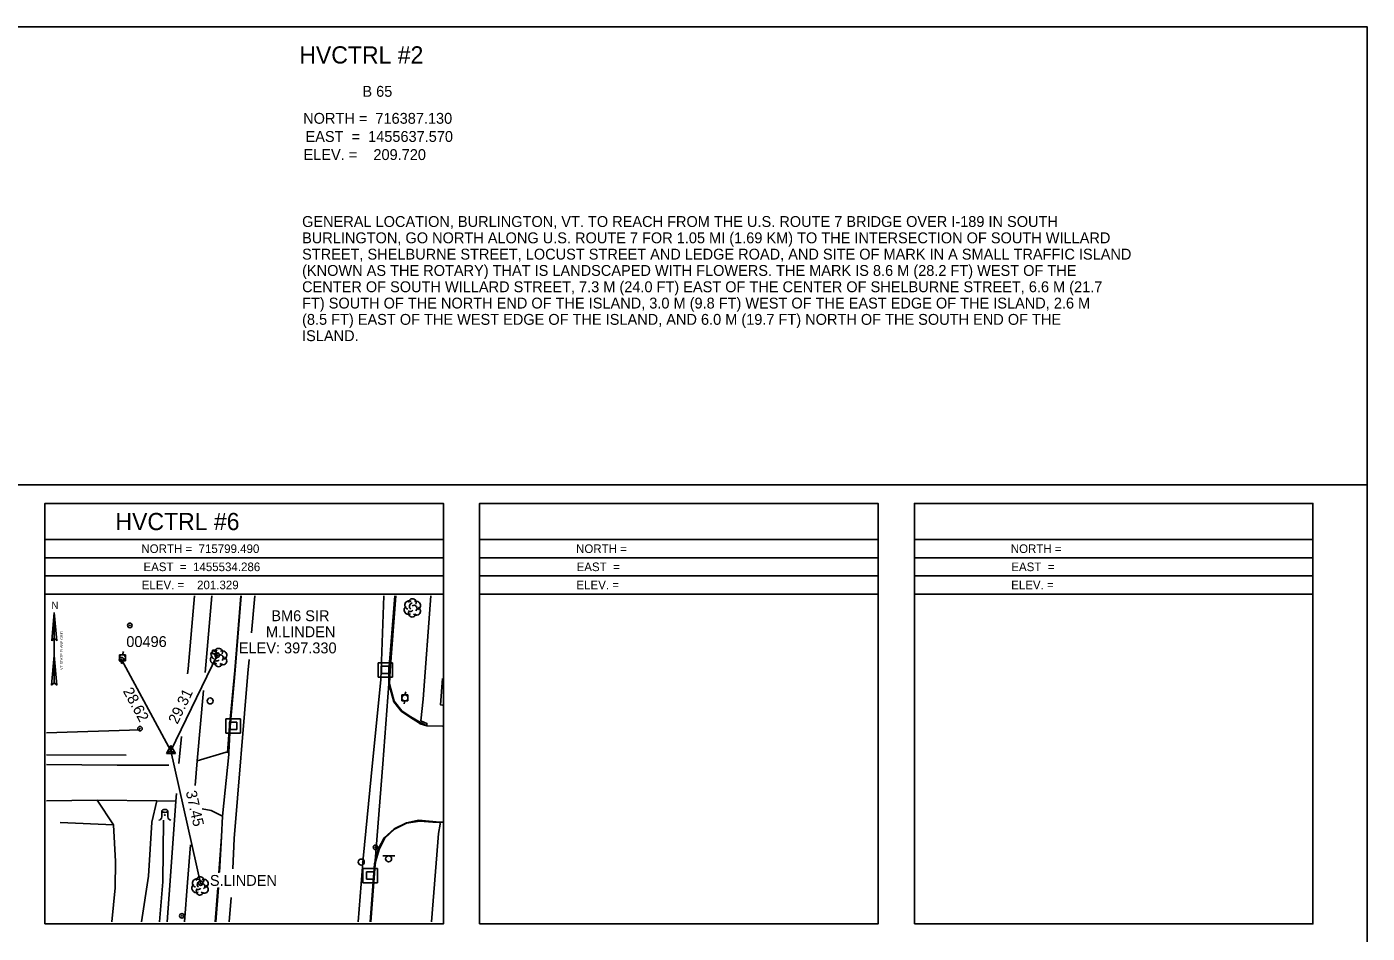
# Model space of a CAD drawing. Extents: x 1454512 to 1455152, y 715836 to 716256.
# Drawn here: x 1454782.2 to 1455152.2, y 716005.4 to 716255.5 of the extents above; entities that cross this region are included whole.
import ezdxf

# ---------------------------------------------------------------- set-up
doc = ezdxf.new("R2010")
doc.units = 0
for name, color, linetype in [('C_C', 7, 'Continuous'), ('CBP', 7, 'Continuous'), ('CPBM', 7, 'Continuous'), ('CPSM', 7, 'Continuous'), ('Default', 7, 'Continuous'), ('DS', 7, 'Continuous'), ('L_C', 7, 'Continuous'), ('LAHR', 7, 'Continuous'), ('LAPB', 7, 'Continuous'), ('LFNC', 7, 'Continuous'), ('LTD', 7, 'Continuous'), ('LTS', 7, 'Continuous'), ('MPIP', 7, 'Continuous'), ('NBL1', 7, 'Continuous'), ('NBL2', 7, 'Continuous'), ('NNA_P', 7, 'Continuous'), ('PET', 7, 'Continuous'), ('PSP', 7, 'Continuous'), ('RC', 7, 'Continuous'), ('RDG', 7, 'Continuous'), ('RDP', 7, 'Continuous'), ('RSW', 7, 'Continuous'), ('SSGN', 7, 'Continuous'), ('U_C', 7, 'Continuous'), ('UP', 7, 'Continuous'), ('UPGW', 7, 'Continuous'), ('UTMH', 7, 'Continuous'), ('UUMH', 7, 'Continuous'), ('UWV', 7, 'Continuous')]:
    doc.layers.add(name, color=color, linetype=linetype)

msp = doc.modelspace()

# ---------------------------------------------------------------- linework, layer by layer
at = {"layer": 'CBP'}
for centre, radius in [((1454808.28, 716080.9), 0.625), ((1454808.28, 716080.9), 0.0833), ((1454834.71, 716082.14), 0.625), ((1454834.71, 716082.14), 0.0833), ((1454830.15, 716019.22), 0.625), ((1454830.15, 716019.22), 0.0833)]:
    msp.add_circle(centre, radius, dxfattribs=at)
at = {"layer": 'CPBM'}
for p, q in [((1454833.46, 716082.5), (1454833.46, 716083.5)), ((1454833.46, 716083.5), (1454834.46, 716083.5)), ((1454834.46, 716082.5), (1454833.46, 716082.5)), ((1454833.96, 716083), (1454833.96, 716083)), ((1454833.96, 716083), (1454833.96, 716083)), ((1454834.46, 716083.5), (1454834.46, 716082.5))]:
    msp.add_line(p, q, dxfattribs=at)
at = {"layer": 'CPSM'}
for p, q in [((1454820.68, 716055.04), (1454821.93, 716057.2)), ((1454820.68, 716055.04), (1454821.93, 716055.76)), ((1454820.68, 716055.04), (1454823.18, 716055.04)), ((1454823.18, 716055.04), (1454821.93, 716057.2)), ((1454821.93, 716055.76), (1454821.93, 716057.2)), ((1454821.93, 716055.76), (1454821.93, 716055.76)), ((1454821.93, 716055.76), (1454823.18, 716055.04))]:
    msp.add_line(p, q, dxfattribs=at)
at = {"layer": 'Default'}
for p, q in [((1454808.28, 716080.9), (1454821.93, 716055.76)), ((1454821.93, 716055.76), (1454834.71, 716082.14)), ((1454821.93, 716055.76), (1454830.15, 716019.22))]:
    msp.add_line(p, q, dxfattribs=at)
at = {"layer": 'DS'}
for p, q in [((1454879.11, 716080.07), (1454883.11, 716080.07)), ((1454879.11, 716076.07), (1454879.11, 716080.07)), ((1454880.11, 716077.07), (1454880.11, 716079.07)), ((1454880.11, 716079.07), (1454882.11, 716079.07)), ((1454882.11, 716077.07), (1454880.11, 716077.07)), ((1454881.11, 716078.07), (1454881.11, 716078.07)), ((1454881.11, 716078.07), (1454881.11, 716078.07)), ((1454882.11, 716079.07), (1454882.11, 716077.07)), ((1454883.11, 716080.07), (1454883.11, 716076.07)), ((1454883.11, 716076.07), (1454879.11, 716076.07)), ((1454837.12, 716064.61), (1454841.12, 716064.61)), ((1454837.12, 716060.61), (1454837.12, 716064.61)), ((1454838.12, 716061.61), (1454838.12, 716063.61)), ((1454838.12, 716063.61), (1454840.12, 716063.61)), ((1454839.12, 716062.61), (1454839.12, 716062.61)), ((1454839.12, 716062.61), (1454839.12, 716062.61)), ((1454840.12, 716063.61), (1454840.12, 716061.61)), ((1454841.12, 716064.61), (1454841.12, 716060.61)), ((1454841.12, 716060.61), (1454837.12, 716060.61)), ((1454840.12, 716061.61), (1454838.12, 716061.61)), ((1454874.95, 716023.32), (1454878.95, 716023.32)), ((1454874.95, 716019.32), (1454874.95, 716023.32)), ((1454875.95, 716020.32), (1454875.95, 716022.32)), ((1454875.95, 716022.32), (1454877.95, 716022.32)), ((1454876.96, 716021.32), (1454876.96, 716021.32)), ((1454876.96, 716021.32), (1454876.96, 716021.32)), ((1454877.95, 716022.32), (1454877.95, 716020.32)), ((1454878.95, 716023.32), (1454878.95, 716019.32)), ((1454878.95, 716019.32), (1454874.95, 716019.32)), ((1454877.95, 716020.32), (1454875.95, 716020.32))]:
    msp.add_line(p, q, dxfattribs=at)
at = {"layer": 'LAHR'}
msp.add_lwpolyline([(1454819.92, 716036.65), (1454819.67, 716019.64), (1454818.78, 716008.54)], dxfattribs=at)
at = {"layer": 'LAPB'}
for points in [[(1454809.55, 716054.57), (1454787.6, 716054.67)], [(1454791.35, 716035.97), (1454806.11, 716035.34)]]:
    msp.add_lwpolyline(points, dxfattribs=at)
at = {"layer": 'LFNC'}
msp.add_lwpolyline([(1454813.33, 716061.51), (1454787.6, 716060.69)], dxfattribs=at)
at = {"layer": 'LTD'}
for p, q in [((1454888.56, 716095.25), (1454888.56, 716095.25)), ((1454888.56, 716095.25), (1454888.56, 716095.25)), ((1454835.08, 716081.55), (1454835.08, 716081.55)), ((1454835.08, 716081.55), (1454835.08, 716081.55)), ((1454829.96, 716018.52), (1454829.96, 716018.52)), ((1454829.96, 716018.52), (1454829.96, 716018.52))]:
    msp.add_line(p, q, dxfattribs=at)
for centre in [(1454888.61, 716096.68), (1454835.13, 716082.98), (1454830, 716019.96)]:
    msp.add_arc(centre, 1.05, 335.5272, 180.9563, dxfattribs=at)
for centre, major_axis, ratio, start_param, end_param in [((1454887.48, 716094.54), (0.58, -1.04), 0.959034, 3.141593, 6.283185), ((1454887.77, 716095.91), (1.21, -0.51), 0.895232, 1.570796, 4.712389), ((1454888.35, 716095.7), (-0.208, -0.792), 0.645439, 3.141593, 6.283185), ((1454889.06, 716095.08), (-0.5, 0.667), 0.989748, 3.141593, 6.283185), ((1454889.56, 716094.41), (-1.09, 0.79), 0.841452, 1.570796, 4.712389), ((1454889.6, 716095.83), (-1.14, -0.48), 0.949671, 1.570796, 4.712389), ((1454888.56, 716093.75), (0.26, 1.06), 0.942809, 1.570796, 4.712389), ((1454888.1, 716094.5), (-0.625, -0.083), 0.423636, 0, 3.141593), ((1454834, 716080.84), (0.58, -1.04), 0.959034, 3.141593, 6.283185), ((1454834.29, 716082.22), (1.21, -0.51), 0.895232, 1.570796, 4.712389), ((1454835.08, 716080.05), (0.26, 1.06), 0.942809, 1.570796, 4.712389), ((1454834.62, 716080.8), (-0.625, -0.083), 0.423636, 0, 3.141593), ((1454834.87, 716082.01), (-0.208, -0.792), 0.645439, 3.141593, 6.283185), ((1454835.58, 716081.38), (-0.5, 0.667), 0.989748, 3.141593, 6.283185), ((1454836.08, 716080.72), (-1.09, 0.79), 0.841452, 1.570796, 4.712389), ((1454836.12, 716082.13), (-1.14, -0.48), 0.949671, 1.570796, 4.712389), ((1454828.87, 716017.81), (0.58, -1.04), 0.959034, 3.141593, 6.283185), ((1454829.16, 716019.19), (1.21, -0.51), 0.895232, 1.570796, 4.712389), ((1454829.5, 716017.77), (-0.625, -0.083), 0.423636, 0, 3.141593), ((1454829.75, 716018.98), (-0.208, -0.792), 0.645439, 3.141593, 6.283185), ((1454830.46, 716018.36), (-0.5, 0.667), 0.989748, 3.141593, 6.283185), ((1454830.96, 716017.69), (-1.09, 0.79), 0.841452, 1.570796, 4.712389), ((1454831, 716019.11), (-1.14, -0.48), 0.949671, 1.570796, 4.712389), ((1454829.96, 716017.02), (0.26, 1.06), 0.942809, 1.570796, 4.712389)]:
    msp.add_ellipse(centre, major_axis=major_axis, ratio=ratio, start_param=start_param, end_param=end_param, dxfattribs=at)
at = {"layer": 'LTS'}
for p, q in [((1454819.44, 716039.16), (1454819.44, 716037.49)), ((1454820.27, 716038.01), (1454820.27, 716038.01)), ((1454820.27, 716038.01), (1454820.27, 716038.01)), ((1454820.27, 716037.99), (1454820.27, 716037.99)), ((1454821.11, 716038.99), (1454821.11, 716039.16)), ((1454821.11, 716039.16), (1454821.11, 716037.49))]:
    msp.add_line(p, q, dxfattribs=at)
msp.add_circle((1454820.27, 716038.01), 0.0833, dxfattribs=at)
for centre, start, end in [((1454818.61, 716037.49), 270, 360), ((1454821.94, 716037.49), 180, 270)]:
    msp.add_arc(centre, 0.833, start, end, dxfattribs=at)
msp.add_ellipse((1454820.27, 716039.16), major_axis=(-0.833, 0), ratio=0.5, dxfattribs=at)
at = {"layer": 'MPIP'}
for radius in [0.625, 0.0833]:
    msp.add_circle((1454813.39, 716061.85), radius, dxfattribs=at)
at = {"layer": 'NBL1'}
msp.add_lwpolyline([(1454512.16, 715835.51), (1455152.16, 715835.51), (1455152.16, 716255.51), (1454512.16, 716255.51)], close=True, dxfattribs=at)
at = {"layer": 'NBL2'}
for p, q in [((1454512.16, 716129.18), (1455152.16, 716129.18)), ((1454897.16, 716114.01), (1454787.16, 716114.01)), ((1455017.16, 716114.01), (1454907.16, 716114.01)), ((1455137.16, 716114.01), (1455027.16, 716114.01)), ((1454897.16, 716109.01), (1454787.16, 716109.01)), ((1455017.16, 716109.01), (1454907.16, 716109.01)), ((1455137.16, 716109.01), (1455027.16, 716109.01)), ((1454897.16, 716104.01), (1454787.16, 716104.01)), ((1455017.16, 716104.01), (1454907.16, 716104.01)), ((1455137.16, 716104.01), (1455027.16, 716104.01)), ((1454897.16, 716099.01), (1454787.16, 716099.01)), ((1455017.16, 716099.01), (1454907.16, 716099.01)), ((1455137.16, 716099.01), (1455027.16, 716099.01))]:
    msp.add_line(p, q, dxfattribs=at)
for points in [[(1454787.16, 716008.01), (1454897.16, 716008.01), (1454897.16, 716124.01), (1454787.16, 716124.01)], [(1454907.16, 716008.01), (1455017.16, 716008.01), (1455017.16, 716124.01), (1454907.16, 716124.01)], [(1455027.16, 716008.01), (1455137.16, 716008.01), (1455137.16, 716124.01), (1455027.16, 716124.01)]]:
    msp.add_lwpolyline(points, close=True, dxfattribs=at)
at = {"layer": 'NNA_P'}
for p, q in [((1454789.05, 716086.1), (1454789.74, 716093.89)), ((1454789.74, 716074.52), (1454789.74, 716093.89)), ((1454790.43, 716086.1), (1454789.74, 716093.89)), ((1454789.05, 716086.1), (1454789.74, 716086.87)), ((1454790.44, 716086.1), (1454789.74, 716086.87)), ((1454789.75, 716082.04), (1454789.02, 716073.88)), ((1454789.74, 716082.04), (1454790.47, 716073.88)), ((1454789.74, 716074.52), (1454789.02, 716073.88)), ((1454789.74, 716074.52), (1454790.47, 716073.88))]:
    msp.add_line(p, q, dxfattribs=at)
at = {"layer": 'PET'}
for points in [[(1454845.14, 716098.52), (1454844.2, 716088.3)], [(1454873.63, 716008.54), (1454875.04, 716026), (1454877.61, 716052.43), (1454879.88, 716075.33), (1454880.7, 716098.52)], [(1454843.53, 716080.98), (1454843.19, 716077.2), (1454839.38, 716031.53), (1454839, 716023.21)], [(1454896.9, 716062.53), (1454892.63, 716062.65), (1454890.78, 716063.22), (1454890.27, 716063.58), (1454888.08, 716064.93), (1454885.53, 716066.68), (1454883.5, 716069.31), (1454882.06, 716074.22)], [(1454878.29, 716025.43), (1454879.26, 716028.76), (1454880.85, 716031.78), (1454883.54, 716034.18), (1454887, 716035.91), (1454890.31, 716036.64), (1454894.25, 716036.27), (1454896.15, 716036.09), (1454896.9, 716036.07)], [(1454838.58, 716015.32), (1454838.06, 716008.54)]]:
    msp.add_lwpolyline(points, dxfattribs=at)
at = {"layer": 'PSP'}
for points in [[(1454841.36, 716098.52), (1454839.71, 716078), (1454838.33, 716062.5), (1454837.89, 716055.35), (1454837.89, 716054.72), (1454836.15, 716037.71), (1454835.94, 716032.05), (1454835.32, 716022.23)], [(1454876.91, 716008.54), (1454878.14, 716024.59), (1454878.29, 716025.43), (1454880.42, 716052.13), (1454882.06, 716074.22), (1454882.14, 716077.91), (1454883.78, 716098.52)], [(1454835.06, 716018.01), (1454834.33, 716008.54)]]:
    msp.add_lwpolyline(points, dxfattribs=at)
at = {"layer": 'RC'}
for points in [[(1454841.2, 716098.52), (1454839.61, 716077.94), (1454838.13, 716062.59), (1454837.6, 716055.32), (1454837.22, 716055.38)], [(1454890.93, 716064.06), (1454892.61, 716063.31), (1454892.63, 716062.65), (1454890.38, 716063.81), (1454888.19, 716065.1), (1454885.69, 716066.78), (1454883.61, 716069.48), (1454882.27, 716074.26), (1454882.48, 716077.93), (1454884.01, 716098.52)], [(1454877.11, 716008.54), (1454878.33, 716024.38), (1454878.5, 716025.42), (1454879.45, 716028.54), (1454880.99, 716031.62), (1454883.68, 716034.1), (1454887, 716035.8), (1454890.66, 716036.36), (1454894.24, 716036.09), (1454896.15, 716036.09), (1454896.24, 716035.49)], [(1454835.94, 716032.05), (1454835.17, 716022.06)], [(1454834.85, 716017.9), (1454834.13, 716008.54)]]:
    msp.add_lwpolyline(points, dxfattribs=at)
at = {"layer": 'RDG'}
for points in [[(1454801.57, 716042.16), (1454806.11, 716035.34), (1454806.6, 716025.24), (1454806.51, 716017.9), (1454805.59, 716008.54)], [(1454813.85, 716008.54), (1454815.79, 716021.19), (1454816.65, 716036.02), (1454818.05, 716041.94)]]:
    msp.add_lwpolyline(points, dxfattribs=at)
at = {"layer": 'RDP'}
for points in [[(1454837.22, 716055.38), (1454829.17, 716052.96)], [(1454787.6, 716052), (1454807.08, 716051.82), (1454821.41, 716051.8)], [(1454787.6, 716041.94), (1454801.57, 716042.16), (1454818.05, 716041.94), (1454823.3, 716041.87)], [(1454830.57, 716039.74), (1454833.01, 716039.31), (1454836.15, 716037.71)]]:
    msp.add_lwpolyline(points, dxfattribs=at)
at = {"layer": 'RSW'}
for points in [[(1454828.42, 716098.52), (1454826.66, 716078.36), (1454826.53, 716076.98)], [(1454833.22, 716098.52), (1454831.42, 716077.38)], [(1454890.93, 716064.06), (1454891.61, 716070.01), (1454893.68, 716098.52)], [(1454896.9, 716068.36), (1454896.36, 716068.41), (1454896.9, 716075.72)], [(1454830.96, 716072.4), (1454829.17, 716052.96), (1454828.62, 716046.21)], [(1454824.83, 716059.73), (1454824.09, 716052.25)], [(1454823.46, 716044.01), (1454823.3, 716041.87), (1454821.75, 716019.83), (1454820.87, 716008.54)], [(1454893.86, 716008.54), (1454895.61, 716030.58), (1454895.76, 716032.91), (1454896.24, 716035.49)], [(1454827.32, 716029.79), (1454826.52, 716019.41), (1454825.73, 716008.54)]]:
    msp.add_lwpolyline(points, dxfattribs=at)
at = {"layer": 'SSGN'}
for p, q in [((1454880.4, 716026.78), (1454883.73, 716026.78)), ((1454882.04, 716025.95), (1454882.04, 716025.95))]:
    msp.add_line(p, q, dxfattribs=at)
msp.add_circle((1454882.04, 716025.95), 0.833, dxfattribs=at)
at = {"layer": 'UP'}
for p, q in [((1454807.73, 716080.61), (1454807.73, 716082.27)), ((1454807.73, 716082.27), (1454809.39, 716082.27)), ((1454809.39, 716080.61), (1454807.73, 716080.61)), ((1454808.31, 716079.77), (1454808.56, 716080.61)), ((1454808.81, 716083.11), (1454808.56, 716082.27)), ((1454808.56, 716081.44), (1454808.56, 716081.44)), ((1454809.39, 716082.27), (1454809.39, 716080.61)), ((1454885.72, 716069.5), (1454885.72, 716071.17)), ((1454885.72, 716071.17), (1454887.38, 716071.17)), ((1454887.38, 716069.5), (1454885.72, 716069.5)), ((1454886.3, 716068.67), (1454886.55, 716069.5)), ((1454886.8, 716072), (1454886.55, 716071.17)), ((1454886.55, 716070.34), (1454886.55, 716070.34)), ((1454887.38, 716071.17), (1454887.38, 716069.5))]:
    msp.add_line(p, q, dxfattribs=at)
for centre in [(1454808.56, 716081.44), (1454886.55, 716070.34)]:
    msp.add_circle(centre, 0.833, dxfattribs=at)
at = {"layer": 'UPGW'}
for radius in [0.625, 0.0833]:
    msp.add_circle((1454810.59, 716090.35), radius, dxfattribs=at)
at = {"layer": 'UTMH'}
for p, q in [((1454832.77, 716069.51), (1454832.77, 716069.51)), ((1454833.6, 716069.51), (1454833.6, 716069.51))]:
    msp.add_line(p, q, dxfattribs=at)
msp.add_circle((1454832.77, 716069.51), 0.833, dxfattribs=at)
at = {"layer": 'UUMH'}
for p, q in [((1454874.49, 716025.04), (1454874.49, 716025.04)), ((1454875.33, 716025.04), (1454875.33, 716025.04))]:
    msp.add_line(p, q, dxfattribs=at)
msp.add_circle((1454874.49, 716025.04), 0.833, dxfattribs=at)
at = {"layer": 'UWV'}
for centre, radius in [((1454878.41, 716029.11), 0.625), ((1454878.41, 716029.11), 0.0833), ((1454824.97, 716010.23), 0.625), ((1454824.97, 716010.23), 0.0833)]:
    msp.add_circle(centre, radius, dxfattribs=at)

# ---------------------------------------------------------------- texts
at = {"layer": 'C_C'}
for s, p in [('BM6 SIR', (1454849.66, 716091.52)), ('M.LINDEN', (1454848.17, 716087.08)), ('ELEV: 397.330', (1454840.68, 716082.64))]:
    msp.add_text(s, height=3, dxfattribs=at).set_placement(p)
at = {"layer": 'Default'}
for s, p in [('GENERAL LOCATION, BURLINGTON, VT. TO REACH FROM THE U.S. ROUTE 7 BRIDGE OVER I-189 IN SOUTH ', (1454858.15, 716200.29)), ('BURLINGTON, GO NORTH ALONG U.S. ROUTE 7 FOR 1.05 MI (1.69 KM) TO THE INTERSECTION OF SOUTH WILLARD ', (1454858.15, 716195.79)), ('STREET, SHELBURNE STREET, LOCUST STREET AND LEDGE ROAD, AND SITE OF MARK IN A SMALL TRAFFIC ISLAND ', (1454858.15, 716191.29)), ('(KNOWN AS THE ROTARY) THAT IS LANDSCAPED WITH FLOWERS. THE MARK IS 8.6 M (28.2 FT) WEST OF THE ', (1454858.15, 716186.79)), ('CENTER OF SOUTH WILLARD STREET, 7.3 M (24.0 FT) EAST OF THE CENTER OF SHELBURNE STREET, 6.6 M (21.7 ', (1454858.15, 716182.29)), ('FT) SOUTH OF THE NORTH END OF THE ISLAND, 3.0 M (9.8 FT) WEST OF THE EAST EDGE OF THE ISLAND, 2.6 M ', (1454858.15, 716177.79)), ('(8.5 FT) EAST OF THE WEST EDGE OF THE ISLAND, AND 6.0 M (19.7 FT) NORTH OF THE SOUTH END OF THE ', (1454858.15, 716173.29)), ('ISLAND. ', (1454858.15, 716168.79))]:
    msp.add_text(s, height=3, dxfattribs=at).set_placement(p)
for s, rotation, p in [('28.62', 298.5054, (1454808.6, 716072.25)), ('29.31', 64.1576, (1454823.73, 716062.9)), ('37.45', 282.6796, (1454826.02, 716044.44))]:
    msp.add_text(s, height=3, rotation=rotation, dxfattribs=at).set_placement(p)
at = {"layer": 'L_C'}
msp.add_text('S.LINDEN', height=3, dxfattribs=at).set_placement((1454832.7, 716018.49))
at = {"layer": 'NBL2'}
for s, height, p in [('     HVCTRL #2     ', 4.75, (1454848.56, 716245.39)), ('    B 65    ', 3, (1454870.34, 716236.21)), ('NORTH =  716387.130 ', 3, (1454858.44, 716228.76)), ('EAST  =  1455637.570', 3, (1454859.1, 716223.76)), ('ELEV. =    209.720  ', 3, (1454858.55, 716218.76)), ('     HVCTRL #6     ', 4.75, (1454797.81, 716116.64)), ('NORTH =  715799.490 ', 2.375, (1454813.78, 716110.33)), ('NORTH =             ', 2.375, (1454933.78, 716110.33)), ('NORTH =             ', 2.375, (1455053.78, 716110.33)), ('EAST  =  1455534.286', 2.375, (1454814.37, 716105.33)), ('EAST  =             ', 2.375, (1454933.92, 716105.33)), ('EAST  =             ', 2.375, (1455053.92, 716105.33)), ('ELEV. =    201.329  ', 2.375, (1454813.89, 716100.33)), ('ELEV. =             ', 2.375, (1454933.89, 716100.33)), ('ELEV. =             ', 2.375, (1455053.89, 716100.33))]:
    msp.add_text(s, height=height, dxfattribs=at).set_placement(p)
at = {"layer": 'NNA_P'}
msp.add_text('N', height=1.97, dxfattribs=at).set_placement((1454788.98, 716094.9))
msp.add_text('VT STATE PLANE GRID', height=0.7, rotation=90.0204, dxfattribs=at).set_placement((1454792.1, 716078.08))
at = {"layer": 'U_C'}
msp.add_text('00496', height=3, dxfattribs=at).set_placement((1454809.63, 716084.39))

doc.saveas('drawing.dxf')
